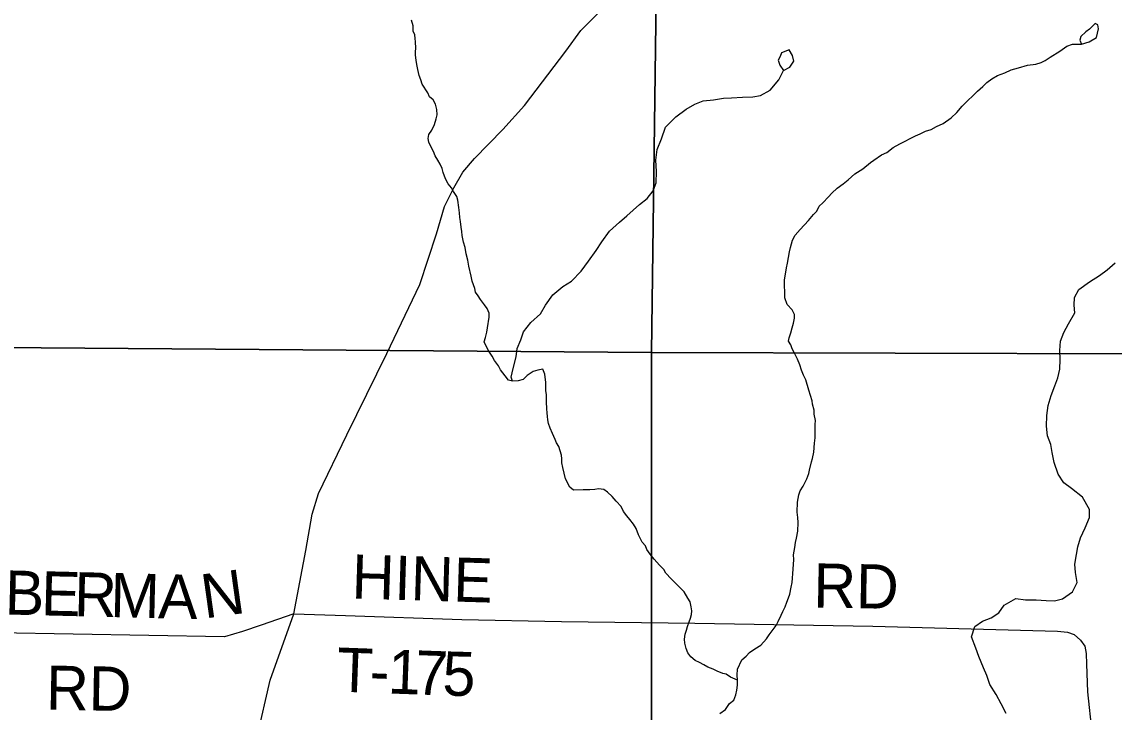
# Model space of a CAD drawing. Extents: x 0 to 34, y -2.3 to 22.
# Drawn here: x 6.815 to 8.222, y 17.875 to 18.764 of the extents above; entities that cross this region are included whole.
import ezdxf

# ---------------------------------------------------------------- set-up
doc = ezdxf.new("R2010")
doc.units = 0
for name, color, linetype in [('GM_X_Minor_River', 7, 'Continuous'), ('GM_X_Section', 7, 'Continuous'), ('GM_X_Township_Road', 7, 'Continuous'), ('GM_X_Township_Road_Text', 7, 'Continuous')]:
    doc.layers.add(name, color=color, linetype=linetype)

msp = doc.modelspace()

# ---------------------------------------------------------------- linework, layer by layer
at = {"layer": 'GM_X_Minor_River'}
for p, q in [((7.3192, 18.7587), (7.3171, 18.7656)), ((7.3194, 18.7515), (7.3192, 18.7587)), ((7.3215, 18.7469), (7.3194, 18.7515)), ((8.1856, 18.7509), (8.179, 18.7449)), ((8.1903, 18.7542), (8.1856, 18.7509)), ((8.1973, 18.7616), (8.1903, 18.7542)), ((8.2011, 18.7596), (8.1973, 18.7616)), ((8.1991, 18.7436), (8.2017, 18.7546)), ((8.2017, 18.7546), (8.2011, 18.7596)), ((7.3218, 18.7423), (7.3215, 18.7469)), ((7.3224, 18.7377), (7.3218, 18.7423)), ((7.3226, 18.7297), (7.3224, 18.7377)), ((8.1608, 18.7325), (8.1684, 18.7349)), ((8.1684, 18.7349), (8.1799, 18.7347)), ((8.179, 18.7449), (8.1777, 18.74)), ((8.1777, 18.74), (8.1799, 18.7347)), ((8.1799, 18.7347), (8.1898, 18.7378)), ((8.1898, 18.7378), (8.1991, 18.7436)), ((7.3224, 18.7206), (7.3225, 18.7252)), ((7.323, 18.7145), (7.3224, 18.7206)), ((7.3225, 18.7252), (7.3226, 18.7297)), ((7.7934, 18.7238), (7.7917, 18.7189)), ((7.8034, 18.7277), (7.7934, 18.7238)), ((7.8078, 18.7203), (7.8034, 18.7277)), ((8.1395, 18.7182), (8.1518, 18.7259)), ((8.1518, 18.7259), (8.1608, 18.7325)), ((7.324, 18.7088), (7.323, 18.7145)), ((7.3253, 18.7023), (7.324, 18.7088)), ((7.7917, 18.7189), (7.7893, 18.7144)), ((7.7893, 18.7144), (7.7914, 18.7078)), ((7.7914, 18.7078), (7.7962, 18.7009)), ((7.8043, 18.7052), (7.8095, 18.7131)), ((7.8095, 18.7131), (7.8078, 18.7203)), ((8.0988, 18.7044), (8.1103, 18.7079)), ((8.1103, 18.7079), (8.121, 18.7092)), ((8.121, 18.7092), (8.1279, 18.7113)), ((8.1279, 18.7113), (8.1333, 18.7138)), ((8.1333, 18.7138), (8.1395, 18.7182)), ((7.327, 18.6946), (7.3253, 18.7023)), ((7.3291, 18.6889), (7.327, 18.6946)), ((7.7902, 18.6892), (7.7962, 18.7009)), ((7.7962, 18.7009), (7.8043, 18.7052)), ((8.0646, 18.6904), (8.0719, 18.6944)), ((8.0719, 18.6944), (8.0811, 18.698)), ((8.0811, 18.698), (8.0892, 18.702)), ((8.0892, 18.702), (8.0988, 18.7044)), ((7.3309, 18.6835), (7.3291, 18.6889)), ((7.3382, 18.6723), (7.3309, 18.6835)), ((7.7792, 18.6758), (7.7902, 18.6892)), ((8.0459, 18.6742), (8.0529, 18.6805)), ((8.0529, 18.6805), (8.058, 18.6857)), ((8.058, 18.6857), (8.0646, 18.6904)), ((7.3404, 18.6673), (7.3382, 18.6723)), ((7.3452, 18.6633), (7.3404, 18.6673)), ((7.7062, 18.6633), (7.7188, 18.6653)), ((7.7188, 18.6653), (7.7291, 18.6658)), ((7.7291, 18.6658), (7.7432, 18.6665)), ((7.7432, 18.6665), (7.7565, 18.6673)), ((7.7565, 18.6673), (7.7664, 18.6689)), ((7.7664, 18.6689), (7.7792, 18.6758)), ((8.0341, 18.6627), (8.0396, 18.6679)), ((8.0396, 18.6679), (8.0459, 18.6742)), ((7.3481, 18.6575), (7.3452, 18.6633)), ((7.3498, 18.651), (7.3481, 18.6575)), ((7.3504, 18.6438), (7.3498, 18.651)), ((7.6577, 18.6414), (7.6709, 18.6514)), ((7.6709, 18.6514), (7.6821, 18.6575)), ((7.6821, 18.6575), (7.6929, 18.6618)), ((7.6929, 18.6618), (7.7062, 18.6633)), ((8.0193, 18.6471), (8.0263, 18.6549)), ((8.0263, 18.6549), (8.0341, 18.6627)), ((7.3466, 18.6313), (7.3491, 18.6389)), ((7.3491, 18.6389), (7.3504, 18.6438)), ((7.6444, 18.6281), (7.6577, 18.6414)), ((8.0018, 18.6327), (8.0119, 18.6401)), ((8.0119, 18.6401), (8.0193, 18.6471)), ((7.3394, 18.6186), (7.3434, 18.6242)), ((7.3434, 18.6242), (7.3466, 18.6313)), ((7.6391, 18.613), (7.6444, 18.6281)), ((7.9721, 18.6194), (7.9791, 18.623)), ((7.9791, 18.623), (7.9864, 18.6251)), ((7.9864, 18.6251), (7.9933, 18.6288)), ((7.9933, 18.6288), (8.0018, 18.6327)), ((7.3386, 18.6133), (7.3394, 18.6186)), ((7.3396, 18.6087), (7.3386, 18.6133)), ((7.3424, 18.6022), (7.3396, 18.6087)), ((7.6334, 18.5995), (7.6391, 18.613)), ((7.9459, 18.6068), (7.966, 18.6169)), ((7.966, 18.6169), (7.9721, 18.6194)), ((7.3453, 18.5967), (7.3424, 18.6022)), ((7.3475, 18.5914), (7.3453, 18.5967)), ((7.6319, 18.5858), (7.6334, 18.5995)), ((7.9223, 18.5925), (7.9293, 18.5954)), ((7.9293, 18.5954), (7.9374, 18.602)), ((7.9374, 18.602), (7.9459, 18.6068)), ((7.3511, 18.5856), (7.3475, 18.5914)), ((7.354, 18.5805), (7.3511, 18.5856)), ((7.3566, 18.5748), (7.354, 18.5805)), ((7.6326, 18.571), (7.6319, 18.5858)), ((7.8983, 18.5745), (7.908, 18.5826)), ((7.908, 18.5826), (7.9126, 18.5856)), ((7.9126, 18.5856), (7.9223, 18.5925)), ((7.3579, 18.5698), (7.3566, 18.5748)), ((7.3608, 18.5617), (7.3579, 18.5698)), ((7.6322, 18.5565), (7.6326, 18.571)), ((7.8796, 18.5605), (7.8878, 18.5679)), ((7.8878, 18.5679), (7.8983, 18.5745)), ((7.3644, 18.5552), (7.3608, 18.5617)), ((7.3688, 18.5501), (7.3644, 18.5552)), ((7.6285, 18.546), (7.6322, 18.5565)), ((7.8653, 18.5495), (7.873, 18.555)), ((7.873, 18.555), (7.8796, 18.5605)), ((7.3714, 18.5451), (7.3688, 18.5501)), ((7.3754, 18.5389), (7.3714, 18.5451)), ((7.3768, 18.5343), (7.3754, 18.5389)), ((7.6206, 18.5363), (7.6285, 18.546)), ((7.8469, 18.5306), (7.854, 18.5384)), ((7.854, 18.5384), (7.8586, 18.5432)), ((7.8586, 18.5432), (7.8653, 18.5495)), ((7.3781, 18.5248), (7.3768, 18.5343)), ((7.379, 18.5179), (7.3781, 18.5248)), ((7.5945, 18.5141), (7.6109, 18.5285)), ((7.6109, 18.5285), (7.6206, 18.5363)), ((7.839, 18.5201), (7.8422, 18.5265)), ((7.8422, 18.5265), (7.8469, 18.5306)), ((7.3796, 18.5118), (7.379, 18.5179)), ((7.3802, 18.5068), (7.3796, 18.5118)), ((7.5848, 18.506), (7.5945, 18.5141)), ((7.8284, 18.5078), (7.8347, 18.5157)), ((7.8347, 18.5157), (7.839, 18.5201)), ((7.3812, 18.4996), (7.3802, 18.5068)), ((7.3818, 18.4939), (7.3812, 18.4996)), ((7.5723, 18.4942), (7.5848, 18.506)), ((7.8112, 18.4889), (7.8175, 18.4963)), ((7.8175, 18.4963), (7.8284, 18.5078)), ((7.3824, 18.4885), (7.3818, 18.4939)), ((7.3841, 18.4801), (7.3824, 18.4885)), ((7.5621, 18.4804), (7.5723, 18.4942)), ((7.8051, 18.4731), (7.8076, 18.4825)), ((7.8076, 18.4825), (7.8112, 18.4889)), ((7.3862, 18.4732), (7.3841, 18.4801)), ((7.3875, 18.4652), (7.3862, 18.4732)), ((7.545, 18.4557), (7.5549, 18.4695)), ((7.5549, 18.4695), (7.5621, 18.4804)), ((7.8015, 18.453), (7.8038, 18.4678)), ((7.8038, 18.4678), (7.8051, 18.4731)), ((7.3896, 18.4568), (7.3875, 18.4652)), ((7.3909, 18.4491), (7.3896, 18.4568)), ((7.5356, 18.4427), (7.545, 18.4557)), ((8.2129, 18.4445), (8.2234, 18.4534)), ((7.394, 18.4365), (7.3909, 18.4491)), ((7.5231, 18.4301), (7.5356, 18.4427)), ((7.7975, 18.4314), (7.7993, 18.4416)), ((7.7993, 18.4416), (7.8002, 18.4469)), ((7.8002, 18.4469), (7.8015, 18.453)), ((8.2032, 18.4372), (8.2129, 18.4445)), ((7.3953, 18.43), (7.394, 18.4365)), ((7.3985, 18.4204), (7.3953, 18.43)), ((7.5122, 18.4231), (7.5231, 18.4301)), ((7.7973, 18.4253), (7.7975, 18.4314)), ((7.7978, 18.415), (7.7973, 18.4253)), ((8.1765, 18.4193), (8.1901, 18.4292)), ((8.1901, 18.4292), (8.2032, 18.4372)), ((7.3995, 18.4158), (7.3985, 18.4204)), ((7.4028, 18.4111), (7.3995, 18.4158)), ((7.4061, 18.4061), (7.4028, 18.4111)), ((7.4895, 18.399), (7.499, 18.4125)), ((7.499, 18.4125), (7.5122, 18.4231)), ((7.798, 18.4086), (7.7978, 18.415)), ((8.1709, 18.4088), (8.1765, 18.4193)), ((7.4113, 18.3995), (7.4061, 18.4061)), ((7.4146, 18.3949), (7.4113, 18.3995)), ((7.4831, 18.3878), (7.4895, 18.399)), ((7.8008, 18.3997), (7.798, 18.4086)), ((7.8075, 18.3931), (7.8008, 18.3997)), ((8.1706, 18.3989), (8.1709, 18.4088)), ((8.1711, 18.3893), (8.1706, 18.3989)), ((7.4171, 18.3887), (7.4146, 18.3949)), ((7.415, 18.3697), (7.4173, 18.3834)), ((7.4173, 18.3834), (7.4171, 18.3887)), ((7.471, 18.3767), (7.4831, 18.3878)), ((7.8104, 18.3869), (7.8075, 18.3931)), ((7.8103, 18.3824), (7.8104, 18.3869)), ((8.1631, 18.3751), (8.1711, 18.3893)), ((7.4141, 18.3644), (7.415, 18.3697)), ((7.4612, 18.3648), (7.471, 18.3767)), ((7.8056, 18.3635), (7.8073, 18.3699)), ((7.8073, 18.3699), (7.8089, 18.3759)), ((7.8089, 18.3759), (7.8103, 18.3824)), ((8.1571, 18.3638), (8.1631, 18.3751)), ((7.4108, 18.352), (7.4124, 18.3573)), ((7.4124, 18.3573), (7.4141, 18.3644)), ((7.4579, 18.3542), (7.4612, 18.3648)), ((7.8026, 18.3525), (7.8035, 18.3571)), ((7.8035, 18.3571), (7.8056, 18.3635)), ((8.153, 18.3525), (8.1571, 18.3638)), ((7.4158, 18.3412), (7.4108, 18.352)), ((7.4209, 18.3334), (7.4158, 18.3412)), ((7.452, 18.3327), (7.4534, 18.3433)), ((7.4534, 18.3433), (7.4579, 18.3542)), ((7.8055, 18.3479), (7.8026, 18.3525)), ((7.8073, 18.3429), (7.8055, 18.3479)), ((7.8099, 18.3383), (7.8073, 18.3429)), ((8.1519, 18.3408), (8.153, 18.3525)), ((8.1523, 18.3293), (8.1519, 18.3408)), ((7.4242, 18.3277), (7.4209, 18.3334)), ((7.4293, 18.3211), (7.4242, 18.3277)), ((7.4481, 18.3175), (7.452, 18.3327)), ((7.8142, 18.3294), (7.8099, 18.3383)), ((7.817, 18.3221), (7.8142, 18.3294)), ((8.152, 18.3168), (8.1523, 18.3293)), ((7.4319, 18.3157), (7.4293, 18.3211)), ((7.4378, 18.3079), (7.4319, 18.3157)), ((7.4455, 18.3062), (7.4481, 18.3175)), ((7.474, 18.3138), (7.4663, 18.3083)), ((7.4798, 18.3152), (7.474, 18.3138)), ((7.4863, 18.3165), (7.4798, 18.3152)), ((7.4888, 18.31), (7.4863, 18.3165)), ((7.8195, 18.3152), (7.817, 18.3221)), ((7.822, 18.309), (7.8195, 18.3152)), ((8.1494, 18.3055), (8.152, 18.3168)), ((7.4422, 18.3025), (7.4378, 18.3079)), ((7.4471, 18.3012), (7.4422, 18.3025)), ((7.4471, 18.3012), (7.4455, 18.3062)), ((7.4543, 18.3018), (7.4471, 18.3012)), ((7.4608, 18.3035), (7.4543, 18.3018)), ((7.4663, 18.3083), (7.4608, 18.3035)), ((7.49, 18.2993), (7.4888, 18.31)), ((7.4903, 18.294), (7.49, 18.2993)), ((7.8249, 18.3029), (7.822, 18.309)), ((7.8287, 18.2895), (7.8249, 18.3029)), ((8.1457, 18.2953), (8.1494, 18.3055)), ((7.4901, 18.2894), (7.4903, 18.294)), ((7.4908, 18.2837), (7.4901, 18.2894)), ((7.8329, 18.276), (7.8287, 18.2895)), ((8.1408, 18.2829), (8.1457, 18.2953)), ((7.4909, 18.2746), (7.4908, 18.2837)), ((7.4914, 18.2654), (7.4909, 18.2746)), ((7.8336, 18.2715), (7.8329, 18.276)), ((7.8357, 18.2638), (7.8336, 18.2715)), ((8.137, 18.27), (8.1408, 18.2829)), ((7.4917, 18.2605), (7.4914, 18.2654)), ((7.4923, 18.2559), (7.4917, 18.2605)), ((7.8355, 18.2588), (7.8357, 18.2638)), ((7.8372, 18.2504), (7.8355, 18.2588)), ((8.1348, 18.2431), (8.1352, 18.2571)), ((8.1352, 18.2571), (8.137, 18.27)), ((7.4926, 18.2513), (7.4923, 18.2559)), ((7.4936, 18.2467), (7.4926, 18.2513)), ((7.4957, 18.2406), (7.4936, 18.2467)), ((7.8371, 18.2455), (7.8372, 18.2504)), ((7.8371, 18.2329), (7.8371, 18.2455)), ((8.1363, 18.2308), (8.1348, 18.2431)), ((7.4989, 18.234), (7.4957, 18.2406)), ((7.5022, 18.2263), (7.4989, 18.234)), ((7.8361, 18.2216), (7.837, 18.2284)), ((7.837, 18.2284), (7.8371, 18.2329)), ((8.1402, 18.2197), (8.1363, 18.2308)), ((7.5039, 18.2217), (7.5022, 18.2263)), ((7.5069, 18.2171), (7.5039, 18.2217)), ((7.5086, 18.2117), (7.5069, 18.2171)), ((7.835, 18.2098), (7.8361, 18.2216)), ((8.1422, 18.2094), (8.1402, 18.2197)), ((7.5104, 18.206), (7.5086, 18.2117)), ((7.5106, 18.2014), (7.5104, 18.206)), ((7.5109, 18.1961), (7.5106, 18.2014)), ((7.8324, 18.1973), (7.8336, 18.2018)), ((7.8336, 18.2018), (7.835, 18.2098)), ((8.1445, 18.1967), (8.1422, 18.2094)), ((7.5119, 18.19), (7.5109, 18.1961)), ((7.5153, 18.1754), (7.5119, 18.19)), ((7.8286, 18.1822), (7.8298, 18.1867)), ((7.8298, 18.1867), (7.8324, 18.1973)), ((8.1498, 18.1814), (8.1445, 18.1967)), ((7.5211, 18.165), (7.5153, 18.1754)), ((7.8213, 18.166), (7.8261, 18.1754)), ((7.8261, 18.1754), (7.8286, 18.1822)), ((8.1571, 18.1702), (8.1498, 18.1814)), ((7.5259, 18.1611), (7.5211, 18.165)), ((7.5381, 18.1615), (7.5259, 18.1611)), ((7.5469, 18.1613), (7.5381, 18.1615)), ((7.5533, 18.1619), (7.5469, 18.1613)), ((7.5579, 18.1625), (7.5533, 18.1619)), ((7.5647, 18.1616), (7.5579, 18.1625)), ((7.5696, 18.1584), (7.5647, 18.1616)), ((7.5756, 18.1529), (7.5696, 18.1584)), ((7.816, 18.1551), (7.8177, 18.16)), ((7.8177, 18.16), (7.8213, 18.166)), ((8.1671, 18.163), (8.1571, 18.1702)), ((8.1813, 18.152), (8.1671, 18.163)), ((7.5807, 18.1467), (7.5756, 18.1529)), ((7.587, 18.1401), (7.5807, 18.1467)), ((7.8139, 18.1327), (7.8143, 18.1456)), ((7.8143, 18.1456), (7.816, 18.1551)), ((8.19, 18.1362), (8.1813, 18.152)), ((7.5903, 18.1335), (7.587, 18.1401)), ((7.5943, 18.1281), (7.5903, 18.1335)), ((7.8145, 18.1259), (7.8139, 18.1327)), ((8.1901, 18.1259), (8.19, 18.1362)), ((7.5983, 18.1231), (7.5943, 18.1281)), ((7.6031, 18.1172), (7.5983, 18.1231)), ((7.6064, 18.1118), (7.6031, 18.1172)), ((7.8151, 18.1194), (7.8145, 18.1259)), ((7.8148, 18.1083), (7.8151, 18.1194)), ((8.1848, 18.1123), (8.1901, 18.1259)), ((7.6096, 18.1034), (7.6064, 18.1118)), ((7.6143, 18.0941), (7.6096, 18.1034)), ((7.813, 18.0993), (7.8148, 18.1083)), ((8.1787, 18.0995), (8.1848, 18.1123)), ((7.6184, 18.0894), (7.6143, 18.0941)), ((7.6202, 18.0845), (7.6184, 18.0894)), ((7.8108, 18.0871), (7.8118, 18.0936)), ((7.8118, 18.0936), (7.813, 18.0993)), ((8.1735, 18.078), (8.175, 18.0882)), ((8.175, 18.0882), (8.1787, 18.0995)), ((7.6246, 18.0786), (7.6202, 18.0845)), ((7.6297, 18.072), (7.6246, 18.0786)), ((7.809, 18.0777), (7.8108, 18.0871)), ((7.8093, 18.0716), (7.809, 18.0777)), ((8.1713, 18.0659), (8.1735, 18.078)), ((7.6367, 18.0642), (7.6297, 18.072)), ((7.6419, 18.0588), (7.6367, 18.0642)), ((7.8086, 18.0594), (7.8093, 18.0716)), ((8.1721, 18.0548), (8.1713, 18.0659)), ((7.6448, 18.0541), (7.6419, 18.0588)), ((7.6515, 18.0467), (7.6448, 18.0541)), ((7.6578, 18.0405), (7.6515, 18.0467)), ((7.8074, 18.0423), (7.8086, 18.0594)), ((8.1741, 18.0422), (8.1721, 18.0548)), ((7.6682, 18.03), (7.6578, 18.0405)), ((7.8043, 18.0272), (7.8061, 18.0363)), ((7.8061, 18.0363), (7.8074, 18.0423)), ((8.1684, 18.0302), (8.1741, 18.0422)), ((7.6729, 18.0218), (7.6682, 18.03)), ((7.6758, 18.0172), (7.6729, 18.0218)), ((7.8006, 18.017), (7.8026, 18.0223)), ((7.8026, 18.0223), (7.8043, 18.0272)), ((8.0805, 18.0128), (8.0952, 18.0215)), ((8.0952, 18.0215), (8.1077, 18.0196)), ((8.1077, 18.0196), (8.1214, 18.0197)), ((8.1214, 18.0197), (8.1343, 18.0189)), ((8.1343, 18.0189), (8.1453, 18.0183)), ((8.1453, 18.0183), (8.1553, 18.021)), ((8.1553, 18.021), (8.1684, 18.0302)), ((7.6772, 18.0107), (7.6758, 18.0172)), ((7.6782, 18.0057), (7.6772, 18.0107)), ((7.6777, 18.0008), (7.6782, 18.0057)), ((7.7933, 18.0001), (7.7953, 18.005)), ((7.7953, 18.005), (7.7985, 18.0106)), ((7.7985, 18.0106), (7.8006, 18.017)), ((8.0734, 18.0031), (8.0805, 18.0128)), ((7.6727, 17.9853), (7.6748, 17.9917)), ((7.6748, 17.9917), (7.6764, 17.9963)), ((7.6764, 17.9963), (7.6777, 18.0008)), ((7.7865, 17.9866), (7.7893, 17.9918)), ((7.7893, 17.9918), (7.7933, 18.0001)), ((8.0425, 17.9856), (8.0522, 17.9922)), ((8.0522, 17.9922), (8.0634, 17.9965)), ((8.0634, 17.9965), (8.0734, 18.0031)), ((7.6688, 17.9691), (7.6694, 17.9755)), ((7.6694, 17.9755), (7.6714, 17.9808)), ((7.6714, 17.9808), (7.6727, 17.9853)), ((7.7778, 17.9746), (7.7817, 17.9799)), ((7.7817, 17.9799), (7.7865, 17.9866)), ((8.0384, 17.9724), (8.0425, 17.9856)), ((7.6691, 17.9641), (7.6688, 17.9691)), ((7.6708, 17.9572), (7.6691, 17.9641)), ((7.7591, 17.9568), (7.7668, 17.9616)), ((7.7668, 17.9616), (7.7742, 17.9694)), ((7.7742, 17.9694), (7.7778, 17.9746)), ((8.0437, 17.9574), (8.0384, 17.9724)), ((7.6729, 17.9515), (7.6708, 17.9572)), ((7.677, 17.9464), (7.6729, 17.9515)), ((7.7427, 17.9424), (7.7482, 17.9472)), ((7.7482, 17.9472), (7.7525, 17.9521)), ((7.7525, 17.9521), (7.7591, 17.9568)), ((8.0475, 17.9467), (8.0437, 17.9574)), ((7.6826, 17.9417), (7.677, 17.9464)), ((7.6882, 17.9393), (7.6826, 17.9417)), ((7.6935, 17.9361), (7.6882, 17.9393)), ((7.6987, 17.9333), (7.6935, 17.9361)), ((7.7055, 17.9305), (7.6987, 17.9333)), ((7.7371, 17.9304), (7.7427, 17.9424)), ((8.0536, 17.9324), (8.0475, 17.9467)), ((7.7107, 17.928), (7.7055, 17.9305)), ((7.7179, 17.9252), (7.7107, 17.928)), ((7.7224, 17.9243), (7.7179, 17.9252)), ((7.7277, 17.9204), (7.7224, 17.9243)), ((7.7371, 17.9163), (7.7277, 17.9204)), ((7.7365, 17.9228), (7.7371, 17.9304)), ((7.7371, 17.9163), (7.7365, 17.9228)), ((8.0579, 17.9224), (8.0536, 17.9324)), ((8.0618, 17.9109), (8.0579, 17.9224)), ((7.736, 17.9034), (7.7369, 17.9099)), ((7.7369, 17.9099), (7.7371, 17.9163)), ((8.0701, 17.8981), (8.0618, 17.9109)), ((7.7322, 17.8906), (7.7347, 17.8974)), ((7.7347, 17.8974), (7.736, 17.9034)), ((8.0763, 17.8858), (8.0701, 17.8981)), ((7.7142, 17.8735), (7.7216, 17.8787)), ((7.7216, 17.8787), (7.7268, 17.8865)), ((7.7268, 17.8865), (7.7322, 17.8906)), ((8.0828, 17.8734), (8.0763, 17.8858))]:
    msp.add_line(p, q, dxfattribs=at)
at = {"layer": 'GM_X_Section'}
for p, q in [((7.6398, 19.3493), (7.6261, 18.3379)), ((7.6261, 18.3379), (7.6398, 19.3493)), ((7.6261, 18.3379), (6.607, 18.3457)), ((6.607, 18.3457), (7.6261, 18.3379)), ((8.6333, 18.3353), (7.6261, 18.3379)), ((7.6261, 18.3379), (7.6261, 17.7098)), ((7.6261, 17.7098), (7.6261, 18.3379)), ((7.6261, 18.3379), (8.6333, 18.3353))]:
    msp.add_line(p, q, dxfattribs=at)
at = {"layer": 'GM_X_Township_Road'}
for p, q in [((7.5351, 18.7524), (7.5593, 18.7767)), ((7.5158, 18.7259), (7.5351, 18.7524)), ((7.4626, 18.6559), (7.5158, 18.7259)), ((7.4347, 18.6252), (7.4626, 18.6559)), ((7.3984, 18.5878), (7.4347, 18.6252)), ((7.3832, 18.5702), (7.3984, 18.5878)), ((7.3718, 18.5502), (7.3832, 18.5702)), ((7.3598, 18.5258), (7.3718, 18.5502)), ((7.3492, 18.4906), (7.3598, 18.5258)), ((7.3279, 18.4258), (7.3492, 18.4906)), ((7.2853, 18.337), (7.3279, 18.4258)), ((7.2338, 18.2323), (7.2853, 18.337)), ((7.1972, 18.1567), (7.2338, 18.2323)), ((7.1894, 18.1302), (7.1972, 18.1567)), ((7.1813, 18.0831), (7.1894, 18.1302)), ((7.1656, 18.0016), (7.1813, 18.0831)), ((7.1656, 18.0016), (7.1237, 17.9871)), ((7.1352, 17.9165), (7.1656, 18.0016)), ((7.1656, 18.0016), (7.2321, 17.9997)), ((7.2321, 17.9997), (7.3818, 17.9946)), ((7.3818, 17.9946), (7.5101, 17.9919)), ((7.5101, 17.9919), (7.6818, 17.9896)), ((7.6818, 17.9896), (7.911, 17.9861)), ((7.0765, 17.9723), (6.7835, 17.9774)), ((7.0997, 17.9789), (7.0765, 17.9723)), ((7.1237, 17.9871), (7.0997, 17.9789)), ((7.911, 17.9861), (8.117, 17.9805)), ((8.117, 17.9805), (8.149, 17.9795)), ((8.149, 17.9795), (8.162, 17.9782)), ((8.162, 17.9782), (8.1703, 17.9751)), ((8.1703, 17.9751), (8.1786, 17.9681)), ((8.1786, 17.9681), (8.1841, 17.9601)), ((8.1841, 17.9601), (8.1858, 17.9506)), ((8.1858, 17.9506), (8.1862, 17.9369)), ((8.1862, 17.9369), (8.1875, 17.9016)), ((7.108, 17.7983), (7.1352, 17.9165)), ((8.1875, 17.9016), (8.1933, 17.8489))]:
    msp.add_line(p, q, dxfattribs=at)

# ---------------------------------------------------------------- texts
at = {"layer": 'GM_X_Township_Road_Text'}
for s, height, rotation, p in [('HINE', 0.05682, 358.2844, (7.2396, 18.0216)), ('RD', 0.05682, 359.0083, (7.8343, 18.01)), ('B', 0.0568, 358.6085, (6.7931, 18.001)), ('E', 0.0568, 358.6095, (6.8397, 17.9999)), ('R', 0.0568, 358.6065, (6.8822, 17.9988)), ('M', 0.0568, 358.6096, (6.9289, 17.9977)), ('A', 0.0568, 358.6952, (6.9906, 17.9962)), ('N', 0.0568, 7.9644, (7.0506, 17.9956)), ('T', 0.0568, 357.891, (7.2202, 17.9018)), ('1', 0.0568, 357.9138, (7.286, 17.8994)), ('7', 0.0568, 357.996, (7.321, 17.8981)), ('5', 0.0568, 358.4452, (7.3565, 17.8968)), ('RD', 0.05682, 359.0118, (6.8463, 17.8785)), ('-', 0.0568, 357.8959, (7.2626, 17.9002))]:
    msp.add_text(s, height=height, rotation=rotation, dxfattribs=at).set_placement(p)

doc.saveas('drawing.dxf')
